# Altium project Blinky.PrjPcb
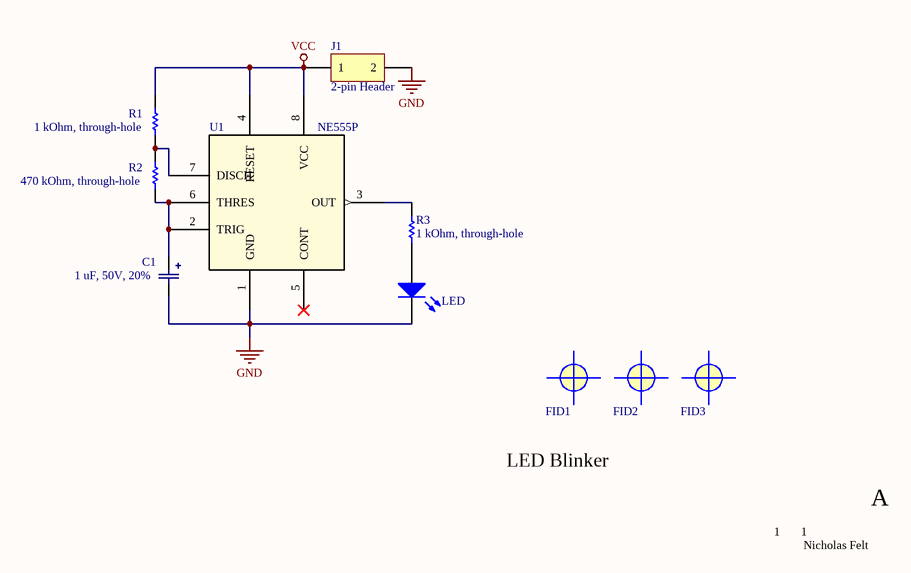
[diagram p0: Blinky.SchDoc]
1 sheet, 10 parts. Net scope: global (net labels, ports and power ports of the same name join across sheets).
Board file: Blinky.PcbDoc

## Sheet Blinky.SchDoc
size A

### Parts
C1  1 uF, 50V, 20%  [U1-E]
FID1  Fiducial Marker  [FIDUCIAL2]  (value not drawn)
FID2  Fiducial Marker  [FIDUCIAL2]  (value not drawn)
FID3  Fiducial Marker  [FIDUCIAL2]  (value not drawn)
J1  2-pin Header  [EMPTY_HDR2X1]
LED  4mm Red LED  [3MM_THRU-HOLE_LED]  (value not drawn)
R1  1 kOhm, through-hole  [RES_THRU_HOLE]
R2  470 kOhm, through-hole  [RES_THRU_HOLE]
R3  1 kOhm, through-hole  [RES_THRU_HOLE]
U1  NE555P  [NE555P]

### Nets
GND: C1.2 J1.2 LED.2(C) U1.1(GND)
VCC: J1.1 R1.2 U1.4(RESET) U1.8(VCC)
NetC1_1: C1.1 R2.1 U1.2(TRIG) U1.6(THRES)
NetLED_1: LED.1(A) R3.1
NetR1_1: R1.1 R2.2 U1.7(DISCH)
NetR3_2: R3.2 U1.3(OUT)

Not connected (* = marked no-connect by the designer): U1 5(CONT)*

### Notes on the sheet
- LED Blinker
- 1
- A
- Nicholas Felt

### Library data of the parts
C1 = UVP1H010MDD1TD: 1 uF, 50V, 20% Capacitor; Vendor: Nichicon; Built_By: EMA_UL_Team; C: Copyright (C) 2015 Accelerated Designs. All rights reserved
FID1-FID3 = FIDUCIAL_2
J1 = Empty_Header_2x1: Header, 2 pin
LED = LTL-4222N: LED 3MM HI-EFF RED TRANSPARENT; Manufacturer 1: Lite-On
R1 R3 = Resistors_1k: Resistor
R2 = Resistors_470k: Resistor
U1 = NE555P: NE555P Timer; Vendor: Texas Instruments; Built_By: EMA_UL_Team; C: Copyright (C) 2015 Accelerated Designs. All rights reserved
